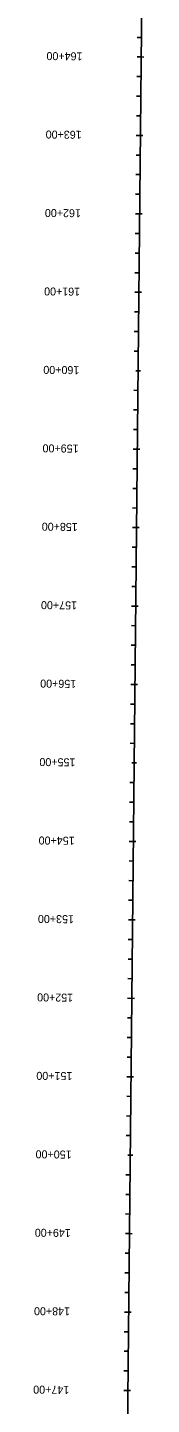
# Model space of a CAD drawing. Extents: x 17535628 to 17537899, y 7333852 to 7342653.
# Drawn here: x 17535652 to 17535794, y 7337366 to 7339121 of the extents above; entities that cross this region are included whole.
import ezdxf

# ---------------------------------------------------------------- set-up
doc = ezdxf.new("R2010")
doc.units = 0
for name, color, linetype in [('Alignment', 7, 'Continuous'), ('Default', 7, 'Continuous'), ('TextAlignmentLrg', 7, 'Continuous'), ('TextAlignmentSml', 7, 'Continuous')]:
    doc.layers.add(name, color=color, linetype=linetype)

msp = doc.modelspace()

# ---------------------------------------------------------------- linework, layer by layer
at = {"layer": 'Alignment'}
for p, q in [((17535771.9, 7337372.7), (17535793.7, 7339556.1)), ((17535763.4, 7336680.4), (17535771.9, 7337372.7))]:
    msp.add_line(p, q, dxfattribs=at)
at = {"layer": 'Default'}
msp.add_line((17535771.9, 7337372.7), (17535794.2, 7339605.8), dxfattribs=at)
at = {"layer": 'TextAlignmentLrg'}
for p, q in [((17535789, 7339083.2), (17535783.5, 7339083.2)), ((17535788, 7338983.2), (17535782.5, 7338983.2)), ((17535787, 7338883.2), (17535781.5, 7338883.2)), ((17535786, 7338783.2), (17535780.5, 7338783.2)), ((17535781.9, 7338683.2), (17535788, 7338683.2)), ((17535784, 7338583.2), (17535778.5, 7338583.3)), ((17535783, 7338483.2), (17535777.5, 7338483.3)), ((17535782, 7338383.2), (17535776.5, 7338383.3)), ((17535781, 7338283.2), (17535775.5, 7338283.3)), ((17535776.9, 7338183.3), (17535783, 7338183.2)), ((17535779, 7338083.2), (17535773.5, 7338083.3)), ((17535778, 7337983.2), (17535772.5, 7337983.3)), ((17535777, 7337883.2), (17535771.5, 7337883.3)), ((17535776, 7337783.2), (17535770.5, 7337783.3)), ((17535771.9, 7337683.3), (17535778.1, 7337683.2)), ((17535774, 7337583.3), (17535768.6, 7337583.3)), ((17535773, 7337483.3), (17535767.6, 7337483.3)), ((17535772, 7337383.3), (17535766.6, 7337383.3))]:
    msp.add_line(p, q, dxfattribs=at)
at = {"layer": 'TextAlignmentSml'}
for p, q in [((17535789.2, 7339108.2), (17535783.7, 7339108.2)), ((17535785.9, 7339083.2), (17535792, 7339083.1)), ((17535788.7, 7339058.2), (17535783.2, 7339058.2)), ((17535788.5, 7339033.2), (17535783, 7339033.2)), ((17535788.2, 7339008.2), (17535782.7, 7339008.2)), ((17535784.9, 7338983.2), (17535791, 7338983.2)), ((17535787.7, 7338958.2), (17535782.2, 7338958.2)), ((17535787.5, 7338933.2), (17535782, 7338933.2)), ((17535787.2, 7338908.2), (17535781.7, 7338908.2)), ((17535783.9, 7338883.2), (17535790, 7338883.2)), ((17535786.7, 7338858.2), (17535781.3, 7338858.2)), ((17535786.5, 7338833.2), (17535781, 7338833.2)), ((17535786.2, 7338808.2), (17535780.8, 7338808.2)), ((17535782.9, 7338783.2), (17535789, 7338783.2)), ((17535785.7, 7338758.2), (17535780.3, 7338758.2)), ((17535785.5, 7338733.2), (17535780, 7338733.2)), ((17535785.2, 7338708.2), (17535779.8, 7338708.2)), ((17535781.9, 7338683.2), (17535788, 7338683.2)), ((17535784.7, 7338658.2), (17535779.3, 7338658.3)), ((17535784.5, 7338633.2), (17535779, 7338633.3)), ((17535784.2, 7338608.2), (17535778.8, 7338608.3)), ((17535780.9, 7338583.2), (17535787, 7338583.2)), ((17535783.7, 7338558.2), (17535778.3, 7338558.3)), ((17535783.5, 7338533.2), (17535778, 7338533.3)), ((17535783.2, 7338508.2), (17535777.8, 7338508.3)), ((17535779.9, 7338483.2), (17535786, 7338483.2)), ((17535782.7, 7338458.2), (17535777.3, 7338458.3)), ((17535782.5, 7338433.2), (17535777, 7338433.3)), ((17535782.2, 7338408.2), (17535776.8, 7338408.3)), ((17535778.9, 7338383.2), (17535785, 7338383.2)), ((17535781.7, 7338358.2), (17535776.3, 7338358.3)), ((17535781.5, 7338333.2), (17535776, 7338333.3)), ((17535781.2, 7338308.2), (17535775.8, 7338308.3)), ((17535777.9, 7338283.2), (17535784, 7338283.2)), ((17535780.7, 7338258.2), (17535775.3, 7338258.3)), ((17535780.5, 7338233.2), (17535775, 7338233.3)), ((17535780.2, 7338208.2), (17535774.8, 7338208.3)), ((17535776.9, 7338183.3), (17535783, 7338183.2)), ((17535779.7, 7338158.2), (17535774.3, 7338158.3)), ((17535779.5, 7338133.2), (17535774, 7338133.3)), ((17535779.2, 7338108.2), (17535773.8, 7338108.3)), ((17535775.9, 7338083.3), (17535782.1, 7338083.2)), ((17535778.7, 7338058.2), (17535773.3, 7338058.3)), ((17535778.5, 7338033.2), (17535773, 7338033.3)), ((17535778.2, 7338008.2), (17535772.8, 7338008.3)), ((17535774.9, 7337983.3), (17535781.1, 7337983.2)), ((17535777.7, 7337958.2), (17535772.3, 7337958.3)), ((17535777.5, 7337933.2), (17535772, 7337933.3)), ((17535777.3, 7337908.2), (17535771.8, 7337908.3)), ((17535773.9, 7337883.3), (17535780.1, 7337883.2)), ((17535776.8, 7337858.2), (17535771.3, 7337858.3)), ((17535776.5, 7337833.2), (17535771, 7337833.3)), ((17535776.3, 7337808.2), (17535770.8, 7337808.3)), ((17535772.9, 7337783.3), (17535779.1, 7337783.2)), ((17535775.8, 7337758.2), (17535770.3, 7337758.3)), ((17535775.5, 7337733.2), (17535770, 7337733.3)), ((17535775.3, 7337708.2), (17535769.8, 7337708.3)), ((17535771.9, 7337683.3), (17535778.1, 7337683.2)), ((17535774.8, 7337658.2), (17535769.3, 7337658.3)), ((17535774.5, 7337633.2), (17535769.1, 7337633.3)), ((17535774.3, 7337608.2), (17535768.8, 7337608.3)), ((17535771, 7337583.3), (17535777.1, 7337583.2)), ((17535773.8, 7337558.3), (17535768.3, 7337558.3)), ((17535773.5, 7337533.3), (17535768.1, 7337533.3)), ((17535773.3, 7337508.3), (17535767.8, 7337508.3)), ((17535770, 7337483.3), (17535776.1, 7337483.2)), ((17535772.8, 7337458.3), (17535767.3, 7337458.3)), ((17535772.5, 7337433.3), (17535767.1, 7337433.3)), ((17535772.3, 7337408.3), (17535766.8, 7337408.3)), ((17535769, 7337383.3), (17535775.1, 7337383.2))]:
    msp.add_line(p, q, dxfattribs=at)

# ---------------------------------------------------------------- texts
at = {"layer": 'TextAlignmentLrg'}
for s, p in [('160+00', (17535710, 7338689)), ('155+00', (17535705, 7338189.1)), ('150+00', (17535700.1, 7337689.1))]:
    msp.add_text(s, height=10.2, rotation=179.4294, dxfattribs=at).set_placement(p)
at = {"layer": 'TextAlignmentSml'}
for s, p in [('164+00', (17535714, 7339089)), ('163+00', (17535713, 7338989)), ('162+00', (17535712, 7338889)), ('161+00', (17535711, 7338789)), ('160+00', (17535710, 7338689)), ('159+00', (17535709, 7338589)), ('158+00', (17535708, 7338489.1)), ('157+00', (17535707, 7338389.1)), ('156+00', (17535706, 7338289.1)), ('155+00', (17535705, 7338189.1)), ('154+00', (17535704, 7338089.1)), ('153+00', (17535703.1, 7337989.1)), ('152+00', (17535702.1, 7337889.1)), ('151+00', (17535701.1, 7337789.1)), ('150+00', (17535700.1, 7337689.1)), ('149+00', (17535699.1, 7337589.1)), ('148+00', (17535698.1, 7337489.1)), ('147+00', (17535697.1, 7337389.1))]:
    msp.add_text(s, height=10.2, rotation=179.4294, dxfattribs=at).set_placement(p)

doc.saveas('drawing.dxf')
